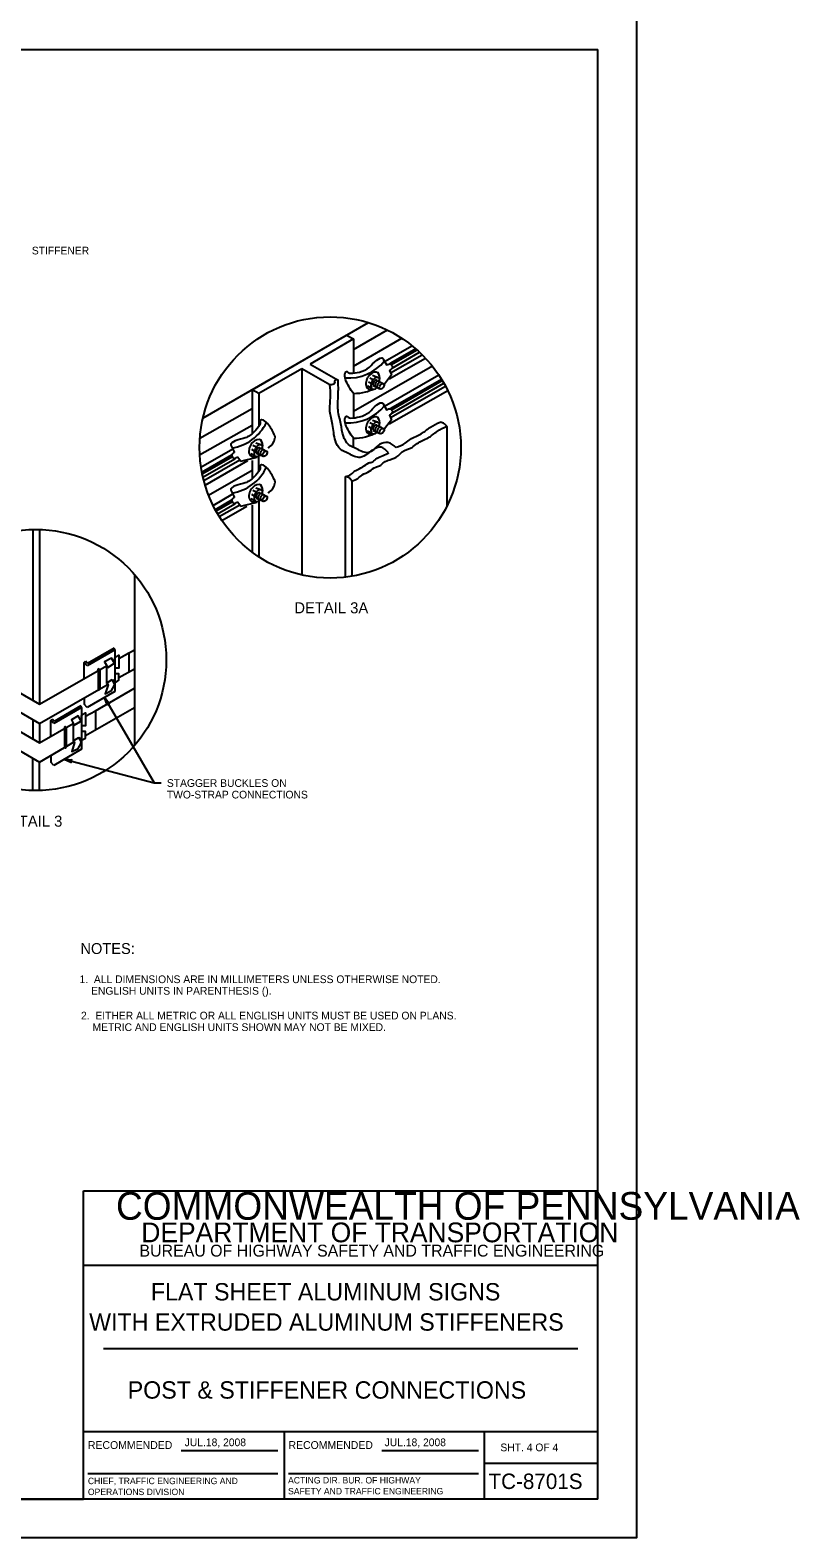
# Model space of a CAD drawing. Extents: x 650495 to 652241, y 298458 to 299646.
# Drawn here: x 651942 to 652241, y 298458 to 299044 of the extents above; entities that cross this region are included whole.
import ezdxf

# ---------------------------------------------------------------- set-up
doc = ezdxf.new("R2010")
doc.units = 0
for name, color, linetype in [('1', 7, 'Continuous'), ('2', 7, 'Continuous'), ('3', 7, 'Continuous'), ('Default', 7, 'Continuous'), ('PLT-BNDY', 7, 'Continuous')]:
    doc.layers.add(name, color=color, linetype=linetype)

# ---------------------------------------------------------------- blocks, each defined once
blk = doc.blocks.new('RARROW')
at = {"layer": '3'}
blk.add_lwpolyline([(-2.2695, 0.285), (-2.184875, 0.12075), (0, 0), (-2.2695, 0.285), (-2.38575, 0.384625), (0, 0), (-2.183125, -0.108), (-2.262875, -0.2705), (0, 0), (-2.38575, -0.379125), (-2.262875, -0.2705)], dxfattribs=at)

msp = doc.modelspace()

# ---------------------------------------------------------------- linework, layer by layer
at = {"layer": '1'}
for p, q in [((651376.31, 299036.63), (652162.31, 299036.63)), ((652162.31, 298472.63), (652162.31, 299036.63)), ((651962.31, 298472.63), (651962.31, 298592.63)), ((651962.31, 298592.63), (652162.31, 298592.63)), ((652162.31, 298563.63), (651962.31, 298563.63)), ((651970.06, 298531.31), (652154.56, 298531.31)), ((651962.31, 298499), (652162.31, 298499)), ((652040.31, 298499), (652040.31, 298472.63)), ((652118.19, 298472.63), (652118.19, 298499)), ((652000.24, 298491.57), (652037.87, 298491.57)), ((652078.24, 298491.57), (652115.87, 298491.57)), ((651963.99, 298482.68), (652037.87, 298482.68)), ((652041.99, 298482.68), (652115.87, 298482.68)), ((652118.19, 298486.63), (652162.31, 298486.63)), ((652162.31, 298472.63), (651376.31, 298472.63)), ((651376.31, 298472.63), (651962.31, 298472.63))]:
    msp.add_line(p, q, dxfattribs=at)
at = {"layer": '2'}
for p, q in [((652008.69, 298893.25), (652073.06, 298930.38)), ((652067.31, 298919.88), (652080.44, 298927.5)), ((652080.44, 298927.5), (652080.44, 298927.5)), ((652027.81, 298904.25), (652064.56, 298925.5)), ((652067.31, 298924), (652050.44, 298914.25)), ((652064.56, 298925.5), (652067.31, 298924)), ((652067.31, 298913.38), (652086.06, 298924.25)), ((652067.31, 298924), (652067.31, 298910.79)), ((652078.81, 298916.13), (652080.19, 298913.75)), ((652079.56, 298915.4), (652089.94, 298921.38)), ((652081.19, 298908.45), (652095.31, 298916.5)), ((652091.56, 298920.13), (652081.59, 298914.4)), ((652081.69, 298910.88), (652093.94, 298917.88)), ((652082.04, 298914.01), (652092.06, 298919.75)), ((652082.31, 298912.63), (652092.94, 298918.88)), ((652047.19, 298912.38), (652030.44, 298902.75)), ((652047.19, 298912.38), (652047.19, 298832.13)), ((652058.05, 298906.12), (652047.19, 298912.38)), ((652050.44, 298914.25), (652061.25, 298908.02)), ((652067.31, 298895.95), (652097.94, 298913.5)), ((652074.69, 298909.88), (652076.56, 298909.13)), ((652082.06, 298910), (652079.31, 298906.44)), ((652079.34, 298897.84), (652100.44, 298910)), ((652081.31, 298911.75), (652082.06, 298910)), ((652027.81, 298904.25), (652027.81, 298887.25)), ((652030.44, 298902.75), (652027.81, 298904.25)), ((652072.69, 298905.75), (652074.44, 298904.75)), ((652073.06, 298907.38), (652074.19, 298906.75)), ((652073.69, 298908.88), (652074.94, 298908.25)), ((652074.19, 298907.75), (652074.19, 298907.75)), ((652074.94, 298905.88), (652077.56, 298904.63)), ((652076.44, 298907.88), (652078.81, 298906.63)), ((652081.19, 298891.02), (652103.92, 298903.98)), ((652081.54, 298896.9), (652101.44, 298908.38)), ((652081.69, 298893.45), (652103.07, 298905.67)), ((652082, 298896.43), (652101.81, 298907.88)), ((652082.44, 298895.22), (652102.44, 298906.75)), ((652030.44, 298902.75), (652030.44, 298890.13)), ((652067.31, 298902.65), (652067.31, 298893.24)), ((652078.81, 298898.7), (652080.19, 298896.32)), ((652007.56, 298885.38), (652027.81, 298897)), ((652074.69, 298892.45), (652076.56, 298891.7)), ((652082.06, 298892.57), (652079.31, 298889.01)), ((652081.31, 298894.32), (652082.06, 298892.57)), ((652007.44, 298878.88), (652027.81, 298890.5)), ((652072.69, 298888.32), (652074.44, 298887.32)), ((652073.06, 298889.95), (652074.19, 298889.32)), ((652073.69, 298891.45), (652074.94, 298890.82)), ((652074.19, 298890.32), (652074.19, 298890.32)), ((652074.94, 298888.45), (652077.56, 298887.2)), ((652076.44, 298890.45), (652078.81, 298889.2)), ((652103.56, 298889.99), (652103.56, 298858.75)), ((652007.94, 298874.13), (652020.31, 298881.25)), ((652019.69, 298882.38), (652021.06, 298879.88)), ((652027.56, 298881.13), (652028.69, 298880.5)), ((652028.19, 298882.63), (652029.56, 298882)), ((652028.69, 298881.5), (652028.69, 298881.5)), ((652029.31, 298883.63), (652031.19, 298882.88)), ((652030.94, 298881.63), (652033.44, 298880.38)), ((652067.31, 298881.77), (652067.31, 298885.22)), ((652008.31, 298872.13), (652019.94, 298878.88)), ((652008.44, 298871.5), (652020.44, 298878.38)), ((652008.69, 298870.25), (652021.19, 298877.38)), ((652009.06, 298868.88), (652023.06, 298877)), ((652009.56, 298867.13), (652026.22, 298876.68)), ((652022.31, 298878), (652023.44, 298876.5)), ((652023.44, 298876.5), (652029.76, 298878.05)), ((652027.31, 298879.5), (652028.94, 298878.5)), ((652027.81, 298876.77), (652027.81, 298869.75)), ((652029.56, 298879.63), (652032.19, 298878.38)), ((652030.44, 298872.63), (652030.44, 298878.37)), ((652010.94, 298863.25), (652027.81, 298873)), ((652064.06, 298870.43), (652064.06, 298831.31)), ((652066.69, 298868.81), (652066.69, 298831.68)), ((652012.69, 298859.25), (652020.31, 298863.75)), ((652019.69, 298864.88), (652021.06, 298862.38)), ((652027.56, 298863.63), (652028.69, 298863)), ((652028.19, 298865.13), (652029.56, 298864.5)), ((652028.69, 298864), (652028.69, 298864)), ((652029.31, 298866.13), (652031.19, 298865.38)), ((652030.94, 298864.13), (652033.44, 298862.88)), ((652013.56, 298857.63), (652019.94, 298861.38)), ((652013.81, 298857.13), (652020.44, 298860.88)), ((652014.44, 298856), (652021.19, 298859.88)), ((652015.06, 298854.88), (652023.06, 298859.5)), ((652016.06, 298853.38), (652025.79, 298858.94)), ((652022.31, 298860.5), (652023.44, 298859)), ((652023.44, 298859), (652029.78, 298860.56)), ((652027.31, 298862), (652028.94, 298861)), ((652027.81, 298859.36), (652027.81, 298841.13)), ((652029.56, 298862.13), (652032.19, 298860.88)), ((652030.44, 298860.89), (652030.44, 298839.25)), ((651942.56, 298849.88), (651942.56, 298783.5)), ((651945.19, 298849.88), (651945.19, 298781.88)), ((651982.06, 298832.38), (651982.06, 298765.88)), ((651962.56, 298798.13), (651963.06, 298798.63)), ((651963.81, 298797.75), (651963.06, 298798.63)), ((651974.44, 298803.13), (651963.69, 298796.88)), ((651974.19, 298803.75), (651963.81, 298797.75)), ((651974.44, 298803.13), (651974.19, 298803.75)), ((651974.44, 298803.13), (651974.44, 298786.88)), ((651976.06, 298799.75), (651979.94, 298801.88)), ((651979.94, 298801.88), (651979.94, 298794.38)), ((651982.06, 298803.13), (651982.06, 298795.63)), ((651962.56, 298791.88), (651962.56, 298798.13)), ((651963.69, 298796.88), (651962.56, 298798.13)), ((651967.94, 298795), (651967.94, 298787.5)), ((651968.56, 298795.38), (651968.56, 298787.88)), ((651969.06, 298795.63), (651969.06, 298795.63)), ((651971.19, 298796.88), (651971.19, 298790)), ((651974.44, 298786.88), (651963.69, 298780.63)), ((651971.19, 298790.13), (651973.44, 298791.5)), ((651982.06, 298788.13), (651982.06, 298780.63)), ((651961.19, 298781.25), (651950.81, 298775.25)), ((651961.44, 298780.63), (651961.19, 298781.25)), ((651962.56, 298784.38), (651962.56, 298781.88)), ((651963.69, 298780.63), (651962.56, 298781.88)), ((651970.38, 298784.52), (651989.81, 298751.38)), ((651942.56, 298776), (651942.56, 298768.5)), ((651949.56, 298775.63), (651950.06, 298776.13)), ((651950.69, 298774.38), (651949.56, 298775.63)), ((651949.56, 298769.38), (651949.56, 298775.63)), ((651950.81, 298775.25), (651950.06, 298776.13)), ((651961.44, 298780.63), (651950.69, 298774.38)), ((651961.44, 298780.63), (651961.44, 298764.38)), ((651963.06, 298777.25), (651966.94, 298779.38)), ((651966.94, 298779.38), (651966.94, 298771.88)), ((651969.06, 298780.63), (651969.06, 298780.63)), ((651945.19, 298774.38), (651945.19, 298766.88)), ((651954.94, 298772.5), (651954.94, 298765)), ((651955.56, 298772.88), (651955.56, 298765.38)), ((651958.19, 298774.38), (651958.19, 298767.5)), ((651958.19, 298767.63), (651960.44, 298769)), ((651961.44, 298764.38), (651950.69, 298758.13)), ((651942.56, 298748.25), (651942.56, 298761)), ((651945.19, 298748.38), (651945.19, 298759.38)), ((651949.56, 298761.88), (651949.56, 298759.38)), ((651950.69, 298758.13), (651949.56, 298759.38)), ((651954.69, 298760.5), (651989.81, 298751.38)), ((651989.81, 298751.38), (651992.44, 298751.38)), ((651989.81, 298751.38), (651992.44, 298751.38))]:
    msp.add_line(p, q, dxfattribs=at)
for points in [[(651908.44, 298803.13), (651945.19, 298781.88), (651971.19, 298796.88)], [(651973.94, 298798.5), (651974.44, 298798.75)], [(651974.44, 298798.75), (651974.44, 298800), (651976.06, 298801), (651976.06, 298796), (651974.44, 298796)], [(651976.06, 298799.75), (651982.06, 298803.13)], [(651908.94, 298795.38), (651945.19, 298774.38), (651971.81, 298789.75)], [(651974.44, 298790.38), (651975.56, 298791), (651976.06, 298791.25), (651976.06, 298793.75), (651974.44, 298793.75)], [(651976.06, 298792.25), (651982.06, 298795.63)], [(651908.44, 298788.13), (651945.19, 298766.88), (651958.31, 298774.38)], [(651966.94, 298779.38), (651982.06, 298788.13)], [(651971.19, 298790), (651971.44, 298789.75), (651971.69, 298789.75), (651971.81, 298789.5), (651970.69, 298786), (651973.19, 298787.25), (651974.19, 298789), (651974.31, 298789.88), (651973.44, 298791.5)], [(651971.81, 298789.5), (651970.69, 298786)], [(651973.44, 298791.5), (651974.31, 298789.88), (651974.44, 298791.25), (651973.81, 298790.88), (651974.19, 298790.25), (651974.19, 298791.13), (651973.94, 298790.88), (651974.19, 298790.5)], [(651973.81, 298790.88), (651974.44, 298791.25)], [(651908.94, 298780.38), (651945.19, 298759.38), (651958.69, 298767.25)], [(651960.94, 298776), (651961.31, 298775.38), (651958.69, 298773.75), (651958.19, 298774.38)], [(651960.94, 298776), (651961.44, 298776.25)], [(651961.44, 298776.25), (651961.44, 298777.5), (651963.06, 298778.5), (651963.06, 298773.5), (651961.44, 298773.5)], [(651963.06, 298769.75), (651982.06, 298780.63)], [(651958.19, 298767.5), (651958.44, 298767.25), (651958.69, 298767.25), (651958.81, 298767), (651957.69, 298763.5), (651960.19, 298764.75), (651961.19, 298766.5), (651961.31, 298767.38), (651960.44, 298769)], [(651960.44, 298769), (651961.31, 298767.38), (651961.44, 298768.75), (651960.81, 298768.38), (651961.19, 298767.75), (651961.19, 298768.63), (651960.94, 298768.38), (651961.19, 298768)], [(651961.44, 298767.88), (651962.56, 298768.5), (651963.06, 298768.75), (651963.06, 298771.25), (651961.44, 298771.25)], [(651958.81, 298767), (651957.69, 298763.5)], [(651960.81, 298768.38), (651961.44, 298768.75)]]:
    msp.add_lwpolyline(points, dxfattribs=at)
for points in [[(651974.31, 298797.88), (651973.19, 298799.88), (651970.44, 298798.38), (651971.69, 298796.25)], [(651961.31, 298775.38), (651960.19, 298777.38), (651957.56, 298775.88), (651958.69, 298773.75)]]:
    msp.add_lwpolyline(points, close=True, dxfattribs=at)
for centre in [(652058.22, 298881.78), (651943.66, 298799.11)]:
    msp.add_circle(centre, 50.81, dxfattribs=at)
for centre, radius, start, end in [((652065.4, 298926.68), 17.87, 265.83165, 321.14733), ((652074.11, 298908.77), 3.36, 347.37836, 39.19138), ((652076.37, 298908.06), 1.04, 326.30993, 77.29289), ((652065.4, 298909.25), 17.87, 265.83165, 321.14733), ((652074.11, 298891.35), 3.36, 347.37836, 39.19138), ((652017.3, 298899.25), 17.87, 278.85259, 334.16826), ((652076.37, 298890.63), 1.04, 326.30993, 77.29289), ((652030.9, 298881.81), 1.04, 326.30993, 77.29289), ((652028.64, 298882.52), 3.36, 347.37836, 39.19138), ((652017.3, 298881.75), 17.87, 278.85259, 334.85047), ((652030.9, 298864.31), 1.04, 326.30993, 77.29289), ((652028.64, 298865.02), 3.36, 347.37836, 39.19138), ((651968.2, 298795.29), 0.328, 12.47174, 227.52972), ((651968.21, 298787.77), 0.321, 223.05577, 16.94568), ((651955.21, 298772.79), 0.328, 12.47174, 227.52972), ((651955.22, 298765.27), 0.321, 223.05577, 16.94568)]:
    msp.add_arc(centre, radius, start, end, dxfattribs=at)
for centre, major_axis, ratio, start_param, end_param in [((652074.87, 298907.73), (-1.86, -3.16), 0.66529, 3.112342, 6.959485), ((652075.82, 298906.78), (-1.19, -2.21), 0.589639, 3.346784, 7.343149), ((652075.7, 298906.88), (-0.705, -0.983), 0.589639, 3.251776, 6.551705), ((652076.49, 298906.57), (-0.705, -0.983), 0.589639, 3.009528, 6.308804), ((652077.28, 298906.05), (-0.705, -0.983), 0.589639, 3.009528, 6.308804), ((652074.87, 298890.3), (-1.86, -3.16), 0.66529, 3.112342, 6.959485), ((652075.82, 298889.35), (-1.19, -2.21), 0.589639, 3.346784, 7.343149), ((652075.7, 298889.46), (-0.705, -0.983), 0.589639, 3.251776, 6.551705), ((652076.49, 298889.14), (-0.705, -0.983), 0.589639, 3.009528, 6.308804), ((652077.28, 298888.62), (-0.705, -0.983), 0.589639, 3.009528, 6.308804), ((652029.4, 298881.48), (-1.86, -3.16), 0.66529, 3.112342, 7.061537), ((652030.35, 298880.53), (-1.19, -2.21), 0.589639, 3.346784, 7.304711), ((652030.23, 298880.63), (-0.705, -0.983), 0.589639, 3.251776, 6.551705), ((652031.02, 298880.32), (-0.705, -0.983), 0.589639, 3.009528, 6.308804), ((652031.82, 298879.8), (-0.705, -0.983), 0.589639, 3.009528, 6.308804), ((652029.4, 298863.98), (-1.86, -3.16), 0.66529, 3.112342, 6.979702), ((652030.35, 298863.03), (-1.19, -2.21), 0.589639, 3.346784, 7.348359), ((652030.23, 298863.13), (-0.705, -0.983), 0.589639, 3.251776, 6.551705), ((652031.02, 298862.82), (-0.705, -0.983), 0.589639, 3.009528, 6.308804), ((652031.82, 298862.3), (-0.705, -0.983), 0.589639, 3.009528, 6.308804)]:
    msp.add_ellipse(centre, major_axis=major_axis, ratio=ratio, start_param=start_param, end_param=end_param, dxfattribs=at)
for centre in [(652078.27, 298905.58), (652078.27, 298888.15), (652032.81, 298879.33), (652032.81, 298861.83)]:
    msp.add_ellipse(centre, major_axis=(-0.705, -0.983), ratio=0.589639, dxfattribs=at)
for points in [[(652066.19, 298910.63), (652069.56, 298911.13), (652073.44, 298913), (652076.31, 298915.75), (652078.69, 298916.38), (652078.81, 298916.13)], [(652067.38, 298902.65), (652064.19, 298908.25), (652064.06, 298910.88), (652064.19, 298911.13), (652064.44, 298911.25)], [(652064.44, 298911.25), (652064.56, 298911.38), (652065.19, 298911), (652066.19, 298910.63)], [(652080.19, 298913.75), (652081.69, 298914.25), (652082.31, 298912.63), (652081.31, 298911.63), (652081.31, 298911.5)], [(652080.81, 298879.88), (652078, 298881.86), (652072.71, 298879.34), (652069.87, 298877.91), (652065.37, 298879.41), (652062.22, 298881.15), (652060.24, 298884.39), (652059.13, 298890.78), (652058.11, 298895.79), (652058.34, 298901.69), (652058.11, 298906.11)], [(652061.32, 298908.01), (652059.98, 298907.81), (652059.9, 298906.75), (652059.27, 298906.28), (652058.13, 298906.12)], [(652083.92, 298881.71), (652080.68, 298883.72), (652077.44, 298882.97), (652072.98, 298879.74), (652068.48, 298881.24), (652065.32, 298882.98), (652063.35, 298886.21), (652062.37, 298890.94), (652061.26, 298896.27), (652061.34, 298902.19), (652061.32, 298908.01)], [(652075.14, 298904.38), (652071.94, 298903.25), (652067.31, 298902.64)], [(652066.19, 298893.2), (652069.56, 298893.7), (652073.44, 298895.57), (652076.31, 298898.32), (652078.69, 298898.95), (652078.81, 298898.7)], [(652031.06, 298892.38), (652030.94, 298892.25), (652030.94, 298891.5), (652030.81, 298890.5)], [(652036.44, 298886.88), (652033.81, 298891.13), (652031.69, 298892.5), (652031.44, 298892.5), (652031.06, 298892.38)], [(652067.38, 298885.23), (652064.19, 298890.82), (652064.06, 298893.45), (652064.19, 298893.7), (652064.44, 298893.82)], [(652064.44, 298893.82), (652064.56, 298893.95), (652065.19, 298893.57), (652066.19, 298893.2)], [(652080.19, 298896.32), (652081.69, 298896.82), (652082.31, 298895.2), (652081.31, 298894.2), (652081.31, 298894.07)], [(652030.81, 298890.5), (652028.69, 298887.88), (652025.19, 298885.5), (652021.31, 298884.38), (652019.56, 298882.63), (652019.69, 298882.38)], [(652034.06, 298881.63), (652034.44, 298881.88), (652036.69, 298885.25), (652036.69, 298886.38), (652036.19, 298887.13)], [(652066.69, 298868.81), (652068.96, 298869.75), (652070.62, 298871.09), (652073.54, 298872.59), (652075.91, 298874.17), (652077.4, 298874.64), (652079.06, 298875.98), (652081.43, 298877.01), (652084.59, 298878.59), (652086.16, 298880.09), (652090.03, 298881.82), (652092, 298883.32), (652096.26, 298885.53), (652099.81, 298888.06), (652103.56, 298890.06)], [(652075.14, 298886.95), (652071.94, 298885.82), (652067.31, 298885.22)], [(652083.82, 298881.88), (652087.39, 298883.44), (652089.36, 298884.94), (652093.62, 298887.15), (652097.17, 298889.68), (652100.92, 298891.67)], [(652103.6, 298889.95), (652102.72, 298890.97), (652100.97, 298891.58)], [(652021.06, 298879.88), (652019.94, 298878.88), (652021.06, 298877.5), (652022.31, 298878), (652022.44, 298877.88)], [(652031.06, 298874.88), (652030.94, 298874.75), (652030.94, 298874), (652030.81, 298873)], [(652036.44, 298869.38), (652033.81, 298873.63), (652031.69, 298875), (652031.44, 298875), (652031.06, 298874.88)], [(652064.05, 298870.42), (652066.32, 298871.36), (652067.98, 298872.71), (652070.9, 298874.21), (652073.27, 298875.78), (652074.76, 298876.26), (652076.42, 298877.6), (652078.79, 298878.63), (652081.02, 298879.71)], [(652030.81, 298873), (652028.69, 298870.38), (652025.19, 298868), (652021.31, 298866.88), (652019.56, 298865.13), (652019.69, 298864.88)], [(652034.06, 298864.13), (652034.44, 298864.38), (652036.69, 298867.75), (652036.69, 298868.88), (652036.19, 298869.63)], [(652066.69, 298868.81), (652065.81, 298869.82), (652064.06, 298870.43)], [(652021.06, 298862.38), (652019.94, 298861.38), (652021.06, 298860), (652022.31, 298860.5), (652022.44, 298860.38)]]:
    msp.add_spline(points, degree=3, dxfattribs=at)
at = {"layer": 'PLT-BNDY'}
msp.add_lwpolyline([(651336.31, 299051.63), (652177.31, 299051.63), (652177.31, 298457.63), (651336.31, 298457.63)], close=True, dxfattribs=at)

# ---------------------------------------------------------------- block references
at = {"layer": '2'}
for p, xscale, yscale, rotation in [((651970.38, 298784.52), 1.2574347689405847, 1.3092961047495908, 120.9356690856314), ((651954.69, 298760.5), 1.257434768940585, 1.3092961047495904, 165.6401293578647)]:
    msp.add_blockref('RARROW', p, dxfattribs=dict(at, xscale=xscale, yscale=yscale, rotation=rotation))

# ---------------------------------------------------------------- texts
at = {"layer": '1'}
for s, height, p in [('COMMONWEALTH OF PENNSYLVANIA', 10.7828, (651974.9, 298581.36)), ('DEPARTMENT OF TRANSPORTATION', 7.6837, (651984.76, 298572.61)), ('BUREAU OF HIGHWAY SAFETY AND TRAFFIC ENGINEERING', 4.6253, (651984.04, 298567.04)), ('FLAT SHEET ALUMINUM SIGNS', 6.75, (651988.47, 298549.97)), ('WITH EXTRUDED ALUMINUM STIFFENERS', 6.75, (651964.47, 298538.22)), ('POST & STIFFENER CONNECTIONS', 6.75, (651979.47, 298511.78)), ('RECOMMENDED', 3.048, (651963.99, 298492.2)), ('RECOMMENDED', 3.048, (652041.99, 298492.2)), ('SHT. 4 OF 4', 3, (652124.4, 298491.31)), ('TC-8701S', 6, (652119.79, 298476.63)), ('OPERATIONS DIVISION', 2.5, (651963.99, 298474.26)), ('CHIEF, TRAFFIC ENGINEERING AND', 2.5, (651963.99, 298478.51))]:
    msp.add_text(s, height=height, dxfattribs=at).set_placement(p)
at = {"layer": '2'}
for s, height, p in [('STIFFENER', 3, (651942.19, 298956.88)), ('DETAIL 3A', 4.3, (652044.26, 298817.27)), ('STAGGER BUCKLES ON', 3, (651994.69, 298749.75)), ('TWO-STRAP CONNECTIONS', 3, (651994.69, 298745.25)), ('DETAIL 3', 4.3, (651929.11, 298734.27)), ('NOTES:', 4.25, (651961.08, 298684.74)), ('1.  ALL DIMENSIONS ARE IN MILLIMETERS UNLESS OTHERWISE NOTED.', 3, (651960.74, 298673.42)), ('    ENGLISH UNITS IN PARENTHESIS ().', 3, (651960.74, 298668.92)), ('2.  EITHER ALL METRIC OR ALL ENGLISH UNITS MUST BE USED ON PLANS.', 3, (651961.31, 298659.29)), ('    METRIC AND ENGLISH UNITS SHOWN MAY NOT BE MIXED.', 3, (651961.31, 298654.79)), ('JUL.18, 2008', 3, (652001.61, 298493.28)), ('JUL.18, 2008', 3, (652079.37, 298493.28))]:
    msp.add_text(s, height=height, dxfattribs=at).set_placement(p)
at = {"layer": 'Default'}
for s, p in [('ACTING DIR. BUR. OF HIGHWAY', (652041.83, 298478.78)), ('SAFETY AND TRAFFIC ENGINEERING', (652041.83, 298474.53))]:
    msp.add_text(s, height=2.5, dxfattribs=at).set_placement(p)

doc.saveas('drawing.dxf')
